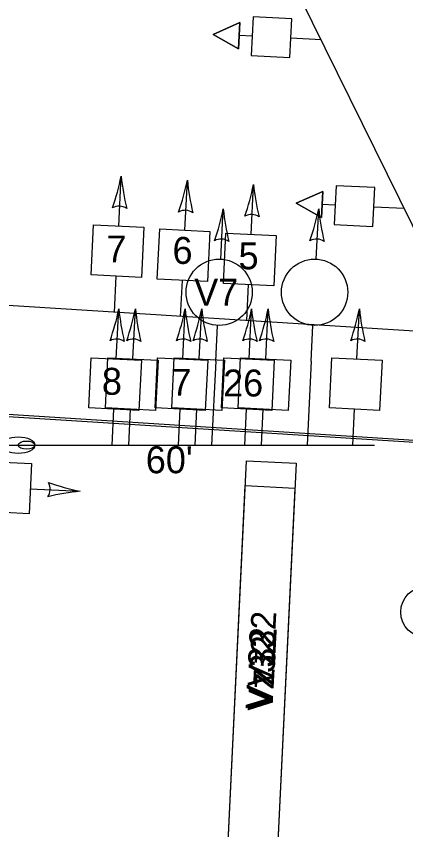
# Model space of a CAD drawing. Extents: x 647787 to 668496, y 640478 to 654412.
# Drawn here: x 659858.1 to 659905.1, y 647329.6 to 647427.8 of the extents above; entities that cross this region are included whole.
import ezdxf

# ---------------------------------------------------------------- set-up
doc = ezdxf.new("R2010")
doc.units = 0
for name, color, linetype in [('TEMP_DETECTION ZONE_Stage 2', 7, 'Continuous'), ('TEMP_DETECTION ZONE_STAGE 3', 7, 'Continuous'), ('TEMP_DETECTION_ZONE_STAGE 5', 7, 'Continuous'), ('TEMP_SIGNAL POLES', 7, 'Continuous'), ('TEMP_SIGNAL_HEAD_STAGE 1A', 7, 'Continuous'), ('TEMP_SIGNAL_HEAD_STAGE 2', 7, 'Continuous'), ('TEMP_SIGNAL_HEAD_STAGE 2 SALEM', 7, 'Continuous'), ('TEMP_SIGNAL_HEAD_Stage 3', 7, 'Continuous'), ('TEMP_SIGNAL_HEAD_STAGE 5', 7, 'Continuous'), ('TEMP_SIGNAL_POLES_STAGE 1A', 7, 'Continuous'), ('TEMP_SIGNAL_POLES_STAGE 1B', 7, 'Continuous'), ('TEMP_SIGNAL_POLES_STAGE 2', 7, 'Continuous'), ('TEMP_SIGNAL_POLES_STAGE 3', 7, 'Continuous'), ('TEMP_SIGNAL_POLES_STAGE 5', 7, 'Continuous'), ('TEXT_TEMP_SIGNAL_POLES_STAGE 2', 7, 'Continuous'), ('TEXT_TEMP_SIGNAL_POLES_STAGE 3', 7, 'Continuous'), ('TEXT_TEMP_SIGNAL_POLES_STAGE 4', 7, 'Continuous'), ('TEXT_TEMP_SIGNAL_POLES_STAGE 5', 7, 'Continuous')]:
    doc.layers.add(name, color=color, linetype=linetype)

msp = doc.modelspace()

# ---------------------------------------------------------------- linework, layer by layer
at = {"layer": 'TEMP_DETECTION ZONE_Stage 2'}
for p, q in [((659883.496, 647324.209), (659885.886, 647374.152)), ((659885.886, 647374.152), (659891.879, 647373.865)), ((659891.879, 647373.865), (659889.489, 647323.922))]:
    msp.add_line(p, q, dxfattribs=at)
at = {"layer": 'TEMP_DETECTION ZONE_STAGE 3'}
for p, q in [((659883.496, 647324.209), (659885.886, 647374.152)), ((659885.886, 647374.152), (659891.879, 647373.865)), ((659891.879, 647373.865), (659889.489, 647323.922))]:
    msp.add_line(p, q, dxfattribs=at)
at = {"layer": 'TEMP_DETECTION_ZONE_STAGE 5'}
for p, q in [((659883.448, 647323.205), (659885.742, 647371.151)), ((659883.448, 647323.205), (659885.742, 647371.151)), ((659885.742, 647371.151), (659891.735, 647370.846)), ((659885.742, 647371.151), (659891.735, 647370.846)), ((659891.735, 647370.846), (659889.441, 647322.901)), ((659891.735, 647370.846), (659889.441, 647322.901))]:
    msp.add_line(p, q, dxfattribs=at)
at = {"layer": 'TEMP_SIGNAL POLES'}
for p, q in [((659935.116, 647343.231), (659859.629, 647496.632)), ((659935.116, 647343.231), (659859.629, 647496.632)), ((659935.116, 647343.231), (659859.629, 647496.632)), ((659935.119, 647343.232), (659859.631, 647496.634))]:
    msp.add_line(p, q, dxfattribs=at)
at = {"layer": 'TEMP_SIGNAL_HEAD_STAGE 1A'}
for p, q in [((659834.949, 647380.916), (659955.369, 647373.287)), ((659834.949, 647380.916), (659955.369, 647373.287)), ((659834.949, 647380.916), (659955.369, 647373.287)), ((659834.962, 647381.165), (659955.606, 647373.523)), ((659834.962, 647381.165), (659955.606, 647373.523)), ((659834.962, 647381.165), (659955.606, 647373.523))]:
    msp.add_line(p, q, dxfattribs=at)
at = {"layer": 'TEMP_SIGNAL_HEAD_STAGE 2'}
for p, q in [((659870.479, 647402.475), (659870.775, 647408.508)), ((659878.463, 647401.969), (659878.76, 647408.002)), ((659886.448, 647401.462), (659886.745, 647407.496)), ((659869.967, 647392.078), (659870.181, 647396.419)), ((659877.952, 647391.571), (659878.166, 647395.913)), ((659885.937, 647391.065), (659886.15, 647395.407))]:
    msp.add_line(p, q, dxfattribs=at)
for points in [[(659873.21, 647396.27), (659867.152, 647396.568), (659867.45, 647402.624), (659873.507, 647402.326)], [(659881.194, 647395.764), (659875.137, 647396.062), (659875.435, 647402.118), (659881.492, 647401.82)], [(659889.179, 647395.258), (659883.122, 647395.556), (659883.42, 647401.611), (659889.477, 647401.313)]]:
    msp.add_lwpolyline(points, close=True, dxfattribs=at)
for centre, radius, start, end in [((659841.888, 647414.345), 29.472, 340.83871, 348.57683), ((659900.098, 647411.483), 29.472, 185.79346, 193.53157), ((659849.873, 647413.839), 29.472, 340.83871, 348.57683), ((659908.082, 647410.977), 29.472, 185.79346, 193.53157), ((659857.857, 647413.333), 29.472, 340.83871, 348.57683), ((659916.067, 647410.471), 29.472, 185.79346, 193.53157), ((659870.517, 647403.248), 1.629, 55.33783, 119.03246), ((659878.502, 647402.742), 1.629, 55.33783, 119.03246), ((659886.487, 647402.235), 1.629, 55.33783, 119.03246)]:
    msp.add_arc(centre, radius, start, end, dxfattribs=at)
at = {"layer": 'TEMP_SIGNAL_HEAD_STAGE 2 SALEM'}
for points in [[(659891.132, 647422.8), (659891.362, 647427.474), (659886.687, 647427.704), (659886.457, 647423.03)], [(659891.132, 647422.8), (659891.362, 647427.474), (659886.687, 647427.704), (659886.457, 647423.03)], [(659891.132, 647422.8), (659891.362, 647427.474), (659886.687, 647427.704), (659886.457, 647423.03)], [(659891.132, 647422.8), (659891.362, 647427.474), (659886.687, 647427.704), (659886.457, 647423.03)], [(659881.873, 647425.598), (659884.937, 647423.867), (659885.092, 647427.02)], [(659881.873, 647425.598), (659884.937, 647423.867), (659885.092, 647427.02)], [(659881.873, 647425.598), (659884.937, 647423.867), (659885.092, 647427.02)], [(659881.873, 647425.598), (659884.937, 647423.867), (659885.092, 647427.02)], [(659901.155, 647402.431), (659901.385, 647407.106), (659896.71, 647407.336), (659896.48, 647402.662)], [(659901.155, 647402.431), (659901.385, 647407.106), (659896.71, 647407.336), (659896.48, 647402.662)], [(659901.155, 647402.431), (659901.385, 647407.106), (659896.71, 647407.336), (659896.48, 647402.662)], [(659901.155, 647402.431), (659901.385, 647407.106), (659896.71, 647407.336), (659896.48, 647402.662)], [(659891.896, 647405.23), (659894.96, 647403.499), (659895.115, 647406.652)], [(659891.896, 647405.23), (659894.96, 647403.499), (659895.115, 647406.652)], [(659891.896, 647405.23), (659894.96, 647403.499), (659895.115, 647406.652)], [(659891.896, 647405.23), (659894.96, 647403.499), (659895.115, 647406.652)]]:
    msp.add_lwpolyline(points, close=True, dxfattribs=at)
for points in [[(659885.092, 647427.02), (659884.937, 647423.867), (659881.873, 647425.598), (659885.092, 647427.02)], [(659885.092, 647427.02), (659884.937, 647423.867), (659881.873, 647425.598), (659885.092, 647427.02)], [(659885.092, 647427.02), (659884.937, 647423.867), (659881.873, 647425.598), (659885.092, 647427.02)], [(659885.092, 647427.02), (659884.937, 647423.867), (659881.873, 647425.598), (659885.092, 647427.02)], [(659886.572, 647425.367), (659885.014, 647425.444)], [(659886.572, 647425.367), (659885.014, 647425.444)], [(659886.572, 647425.367), (659885.014, 647425.444)], [(659886.572, 647425.367), (659885.014, 647425.444)], [(659894.899, 647424.957), (659891.247, 647425.137)], [(659894.899, 647424.957), (659891.247, 647425.137)], [(659894.899, 647424.957), (659891.247, 647425.137)], [(659894.899, 647424.957), (659891.247, 647425.137)], [(659895.115, 647406.652), (659894.96, 647403.499), (659891.896, 647405.23), (659895.115, 647406.652)], [(659895.115, 647406.652), (659894.96, 647403.499), (659891.896, 647405.23), (659895.115, 647406.652)], [(659895.115, 647406.652), (659894.96, 647403.499), (659891.896, 647405.23), (659895.115, 647406.652)], [(659895.115, 647406.652), (659894.96, 647403.499), (659891.896, 647405.23), (659895.115, 647406.652)], [(659896.595, 647404.999), (659895.037, 647405.075)], [(659896.595, 647404.999), (659895.037, 647405.075)], [(659896.595, 647404.999), (659895.037, 647405.075)], [(659896.595, 647404.999), (659895.037, 647405.075)], [(659904.922, 647404.589), (659901.27, 647404.769)], [(659904.922, 647404.589), (659901.27, 647404.769)], [(659904.922, 647404.589), (659901.27, 647404.769)], [(659904.922, 647404.589), (659901.27, 647404.769)]]:
    msp.add_lwpolyline(points, dxfattribs=at)
msp.add_circle((659907.606, 647355.897), 3.089, dxfattribs=at)
msp.add_circle((659907.606, 647355.897), 3.089, dxfattribs=at)
at = {"layer": 'TEMP_SIGNAL_HEAD_Stage 3'}
for p, q in [((659870.479, 647402.475), (659870.775, 647408.508)), ((659878.463, 647401.969), (659878.76, 647408.002)), ((659886.448, 647401.462), (659886.745, 647407.496)), ((659869.967, 647392.078), (659870.181, 647396.419)), ((659877.952, 647391.571), (659878.166, 647395.913)), ((659885.937, 647391.065), (659886.15, 647395.407))]:
    msp.add_line(p, q, dxfattribs=at)
for points in [[(659873.21, 647396.27), (659867.152, 647396.568), (659867.45, 647402.624), (659873.507, 647402.326)], [(659881.194, 647395.764), (659875.137, 647396.062), (659875.435, 647402.118), (659881.492, 647401.82)], [(659889.179, 647395.258), (659883.122, 647395.556), (659883.42, 647401.611), (659889.477, 647401.313)]]:
    msp.add_lwpolyline(points, close=True, dxfattribs=at)
for centre, radius, start, end in [((659841.888, 647414.345), 29.472, 340.83871, 348.57683), ((659900.098, 647411.483), 29.472, 185.79346, 193.53157), ((659849.873, 647413.839), 29.472, 340.83871, 348.57683), ((659908.082, 647410.977), 29.472, 185.79346, 193.53157), ((659857.857, 647413.333), 29.472, 340.83871, 348.57683), ((659916.067, 647410.471), 29.472, 185.79346, 193.53157), ((659870.517, 647403.248), 1.629, 55.33783, 119.03246), ((659878.502, 647402.742), 1.629, 55.33783, 119.03246), ((659886.487, 647402.235), 1.629, 55.33783, 119.03246)]:
    msp.add_arc(centre, radius, start, end, dxfattribs=at)
at = {"layer": 'TEMP_SIGNAL_HEAD_STAGE 5'}
for p, q in [((659882.797, 647398.48), (659883.095, 647404.538)), ((659882.797, 647398.48), (659883.095, 647404.538)), ((659870.19, 647386.435), (659870.487, 647392.468)), ((659870.19, 647386.435), (659870.487, 647392.468)), ((659878.2, 647386.435), (659878.496, 647392.468)), ((659878.2, 647386.435), (659878.496, 647392.468)), ((659886.209, 647386.435), (659886.506, 647392.468)), ((659886.209, 647386.435), (659886.506, 647392.468)), ((659882.191, 647386.165), (659882.404, 647390.49)), ((659882.191, 647386.165), (659882.404, 647390.49)), ((659882.191, 647386.165), (659881.693, 647376.037)), ((659882.191, 647386.165), (659881.693, 647376.037)), ((659869.679, 647376.037), (659869.892, 647380.379)), ((659869.679, 647376.037), (659869.892, 647380.379)), ((659877.688, 647376.037), (659877.902, 647380.379)), ((659877.688, 647376.037), (659877.902, 647380.379)), ((659885.698, 647376.037), (659885.912, 647380.379)), ((659885.698, 647376.037), (659885.912, 647380.379))]:
    msp.add_line(p, q, dxfattribs=at)
for points in [[(659872.921, 647380.23), (659866.864, 647380.528), (659867.161, 647386.584), (659873.219, 647386.286)], [(659872.921, 647380.23), (659866.864, 647380.528), (659867.161, 647386.584), (659873.219, 647386.286)], [(659880.93, 647380.23), (659874.873, 647380.528), (659875.171, 647386.584), (659881.228, 647386.286)], [(659880.93, 647380.23), (659874.873, 647380.528), (659875.171, 647386.584), (659881.228, 647386.286)], [(659888.94, 647380.23), (659882.883, 647380.528), (659883.181, 647386.584), (659889.238, 647386.286)], [(659888.94, 647380.23), (659882.883, 647380.528), (659883.181, 647386.584), (659889.238, 647386.286)]]:
    msp.add_lwpolyline(points, close=True, dxfattribs=at)
msp.add_circle((659882.6, 647394.485), 4, dxfattribs=at)
msp.add_circle((659882.6, 647394.485), 4, dxfattribs=at)
for centre, radius, start, end in [((659854.208, 647410.369), 29.47, 340.8488, 348.58691), ((659854.208, 647410.369), 29.47, 340.8488, 348.58691), ((659912.416, 647407.518), 29.472, 185.80448, 193.54259), ((659912.416, 647407.518), 29.472, 185.80448, 193.54259), ((659882.837, 647399.277), 1.629, 55.33783, 119.03246), ((659882.837, 647399.277), 1.629, 55.33783, 119.03246), ((659841.599, 647398.305), 29.472, 340.83871, 348.57683), ((659841.599, 647398.305), 29.472, 340.83871, 348.57683), ((659899.809, 647395.443), 29.472, 185.79346, 193.53157), ((659899.809, 647395.443), 29.472, 185.79346, 193.53157), ((659849.609, 647398.305), 29.472, 340.83871, 348.57683), ((659849.609, 647398.305), 29.472, 340.83871, 348.57683), ((659907.819, 647395.443), 29.472, 185.79346, 193.53157), ((659907.819, 647395.443), 29.472, 185.79346, 193.53157), ((659857.618, 647398.305), 29.472, 340.83871, 348.57683), ((659857.618, 647398.305), 29.472, 340.83871, 348.57683), ((659915.828, 647395.443), 29.472, 185.79346, 193.53157), ((659915.828, 647395.443), 29.472, 185.79346, 193.53157), ((659870.229, 647387.208), 1.629, 55.33783, 119.03246), ((659870.229, 647387.208), 1.629, 55.33783, 119.03246), ((659878.238, 647387.208), 1.629, 55.33783, 119.03246), ((659878.238, 647387.208), 1.629, 55.33783, 119.03246), ((659886.248, 647387.208), 1.629, 55.33783, 119.03246), ((659886.248, 647387.208), 1.629, 55.33783, 119.03246)]:
    msp.add_arc(centre, radius, start, end, dxfattribs=at)
at = {"layer": 'TEMP_SIGNAL_POLES_STAGE 1A'}
for p, q in [((659894.311, 647398.48), (659894.608, 647404.538)), ((659872.192, 647386.435), (659872.489, 647392.468)), ((659880.202, 647386.435), (659880.499, 647392.468)), ((659888.212, 647386.435), (659888.508, 647392.468)), ((659899.225, 647386.435), (659899.522, 647392.468)), ((659893.705, 647386.165), (659893.918, 647390.49)), ((659893.705, 647386.165), (659893.207, 647376.037)), ((659871.681, 647376.037), (659871.895, 647380.379)), ((659879.691, 647376.037), (659879.904, 647380.379)), ((659887.701, 647376.037), (659887.914, 647380.379)), ((659898.714, 647376.037), (659898.927, 647380.379)), ((659841.36, 647376.037), (659901.36, 647376.037)), ((659859.812, 647370.785), (659865.844, 647370.478))]:
    msp.add_line(p, q, dxfattribs=at)
for points in [[(659874.923, 647380.23), (659868.866, 647380.528), (659869.164, 647386.584), (659875.221, 647386.286)], [(659882.933, 647380.23), (659876.876, 647380.528), (659877.173, 647386.584), (659883.231, 647386.286)], [(659890.943, 647380.23), (659884.885, 647380.528), (659885.183, 647386.584), (659891.24, 647386.286)], [(659901.956, 647380.23), (659895.899, 647380.528), (659896.196, 647386.584), (659902.254, 647386.286)], [(659853.603, 647368.064), (659853.91, 647374.121), (659859.966, 647373.813), (659859.658, 647367.757)]]:
    msp.add_lwpolyline(points, close=True, dxfattribs=at)
msp.add_circle((659894.114, 647394.485), 4, dxfattribs=at)
for centre, radius, start, end in [((659865.721, 647410.369), 29.47, 340.8488, 348.58691), ((659923.93, 647407.518), 29.472, 185.80448, 193.54259), ((659894.351, 647399.277), 1.629, 55.33783, 119.03246), ((659843.602, 647398.305), 29.472, 340.83871, 348.57683), ((659901.811, 647395.443), 29.472, 185.79346, 193.53157), ((659851.611, 647398.305), 29.472, 340.83871, 348.57683), ((659909.821, 647395.443), 29.472, 185.79346, 193.53157), ((659859.621, 647398.305), 29.472, 340.83871, 348.57683), ((659917.831, 647395.443), 29.472, 185.79346, 193.53157), ((659870.634, 647398.305), 29.472, 340.83871, 348.57683), ((659928.844, 647395.443), 29.472, 185.79346, 193.53157), ((659872.231, 647387.208), 1.629, 55.33783, 119.03246), ((659880.241, 647387.208), 1.629, 55.33783, 119.03246), ((659888.251, 647387.208), 1.629, 55.33783, 119.03246), ((659899.264, 647387.208), 1.629, 55.33783, 119.03246), ((659860.585, 647370.745), 1.629, 325.24425, 28.93889), ((659871.729, 647399.356), 29.472, 250.74514, 258.48325), ((659868.772, 647341.151), 29.472, 95.69989, 103.438)]:
    msp.add_arc(centre, radius, start, end, dxfattribs=at)
for centre, major_axis in [((659858.36, 647376.037), (2, 0)), ((659859.36, 647376.037), (-1, 0))]:
    msp.add_ellipse(centre, major_axis=major_axis, ratio=0.5, dxfattribs=at)
at = {"layer": 'TEMP_SIGNAL_POLES_STAGE 1B'}
for p, q in [((659883.448, 647323.205), (659885.742, 647371.151)), ((659885.742, 647371.151), (659891.735, 647370.846)), ((659891.735, 647370.846), (659889.441, 647322.901))]:
    msp.add_line(p, q, dxfattribs=at)
at = {"layer": 'TEMP_SIGNAL_POLES_STAGE 2'}
msp.add_line((659962.344, 647386.22), (659823.607, 647395.017), dxfattribs=at)
at = {"layer": 'TEMP_SIGNAL_POLES_STAGE 3'}
msp.add_line((659967.334, 647385.904), (659823.607, 647395.017), dxfattribs=at)
at = {"layer": 'TEMP_SIGNAL_POLES_STAGE 5'}
msp.add_line((659841.36, 647376.037), (659901.36, 647376.037), dxfattribs=at)
msp.add_line((659841.36, 647376.037), (659901.36, 647376.037), dxfattribs=at)
for centre, major_axis in [((659858.36, 647376.037), (2, 0)), ((659858.36, 647376.037), (2, 0)), ((659859.36, 647376.037), (-1, 0)), ((659859.36, 647376.037), (-1, 0))]:
    msp.add_ellipse(centre, major_axis=major_axis, ratio=0.5, dxfattribs=at)

# ---------------------------------------------------------------- texts
at = {"layer": 'TEMP_DETECTION ZONE_Stage 2'}
msp.add_text('Vz32', height=3, rotation=86.93664, dxfattribs=at).set_placement((659889.018, 647346.795))
at = {"layer": 'TEMP_DETECTION ZONE_STAGE 3'}
msp.add_text('Vz32', height=3, rotation=86.93664, dxfattribs=at).set_placement((659889.018, 647346.795))
at = {"layer": 'TEMP_DETECTION_ZONE_STAGE 5'}
msp.add_text('Vz32', height=3, rotation=86.93664, dxfattribs=at).set_placement((659889.018, 647343.843))
msp.add_text('Vz32', height=3, rotation=86.93664, dxfattribs=at).set_placement((659889.018, 647343.843))
at = {"layer": 'TEMP_SIGNAL_POLES_STAGE 1B'}
msp.add_text('Vz32', height=3.25, rotation=86.93664, dxfattribs=at).set_placement((659889.031, 647344.082))
at = {"layer": 'TEXT_TEMP_SIGNAL_POLES_STAGE 2'}
for s, p in [('7', (659868.992, 647398.076)), ('6', (659876.971, 647397.904)), ('5', (659884.942, 647397.255))]:
    msp.add_text(s, height=3.25, dxfattribs=at).set_placement(p)
at = {"layer": 'TEXT_TEMP_SIGNAL_POLES_STAGE 3'}
for s, p in [('7', (659868.992, 647398.076)), ('6', (659876.971, 647397.904)), ('5', (659884.942, 647397.255))]:
    msp.add_text(s, height=3.25, dxfattribs=at).set_placement(p)
at = {"layer": 'TEXT_TEMP_SIGNAL_POLES_STAGE 4'}
msp.add_text('V7', height=3.25, rotation=359.93402, dxfattribs=at).set_placement((659879.587, 647392.863))
for s, p in [('8', (659868.45, 647382.115)), ('7', (659876.838, 647381.994)), ('26', (659883.076, 647381.908)), ("60'", (659873.747, 647372.646))]:
    msp.add_text(s, height=3.25, dxfattribs=at).set_placement(p)
at = {"layer": 'TEXT_TEMP_SIGNAL_POLES_STAGE 5'}
msp.add_text('V7', height=3.25, rotation=359.93402, dxfattribs=at).set_placement((659879.587, 647392.863))
for s, p in [('8', (659868.45, 647382.115)), ('7', (659876.838, 647381.994)), ('26', (659883.076, 647381.908)), ("60'", (659873.747, 647372.646))]:
    msp.add_text(s, height=3.25, dxfattribs=at).set_placement(p)

doc.saveas('drawing.dxf')
